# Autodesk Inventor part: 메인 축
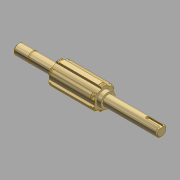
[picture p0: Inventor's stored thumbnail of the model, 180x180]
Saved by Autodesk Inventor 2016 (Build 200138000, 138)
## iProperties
Created: 2015-11
Part Number: 메인 축
Document SubType Name: 모델링
Designer: mdu
Mass: 21.4461 g
Surface Area: 72.5104 cm^2
Volume: 21.4461 cm^3
Density: 1 g/cm^3
Material: 일반
Appearance: 기본값
변환 표준: STEP AP214IS
파일 이름: C:\Users\SeoGD\Desktop\?쒗뿕\硫붿씤 異?.stp
전처리기: Build: 253, Release: 2010 SP1 - Date: Wed 07/29/2009
전송 단위: 밀리미터
불확실성: 0.01
Author: mdu
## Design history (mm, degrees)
sketch "스케치1"
  geometry: L1 (-69.5, 0)-(69.5, 0); L2 (69.5, 0)-(69.5, 5); L3 (69.5, 5)-(55.5, 5); L4 (55.5, 5)-(55.5, 4.8); L5 (55.5, 4.8)-(54.35, 4.8); L6 (54.35, 4.8)-(54.35, 5); L7 (54.35, 5)-(30.5, 5); L8 (30.5, 5)-(30.5, 9); L9 (30.5, 9)-(-13.5, 9); L10 (-13.5, 9)-(-13.5, 7); L11 (-13.5, 7)-(-17.5, 7); L12 (-17.5, 7)-(-17.5, 5); L13 (-17.5, 5)-(-69.5, 5); L14 (-69.5, 5)-(-69.5, 0); 2 further points
  constraints: 28 end point, 9 parallel, 4 collinear, 2 perpendicular, 1 coincident, 1 horizontal, 1 midpoint
  dimensions: "d2" = 1.15 distance between parallel lines of L6 L4; "d3" = 10 diameter of L3 L1; "d4" = 9.6 diameter of L5 L1; "d6" = 44 distance between parallel lines of L10 L8; "d7" = 4 distance between parallel lines of L12 L10; "d8" = 14 diameter of L11 L1; "d9" = 18 diameter of L9 L1; "d33" = 52 distance from line of L12.end L14; "d37" = 39 distance between parallel lines of L8 L2; "d38" = 14 distance between parallel lines of L2 L4
revolve "회전1" sketch "스케치1" stored, may be unused: angle "d10" = 90 deg
sketch "스케치2"
  geometry: L1 (2.5, 10.712)-(2.5, 8.646); L2 (-2.5, 10.712)-(-2.5, 8.646); A1 r 9 centre (0, 0) between (2.5, 8.646) and (-2.5, 8.646) reference; A2 r 11 centre (0, 0) between (2.5, 10.712) and (-2.5, 10.712); 1 further point
  constraints: 4 end point, 4 point on circle, 2 parallel, 1 centre point, 1 coincident, 1 vertical
  dimensions: "d11" = 22 diameter of A2; "d12" = 5 distance between parallel lines of L1 L2
extrude "돌출1" join sketch "스케치2" stored distance "d13" = 10; taper "d14" = 0 deg
chamfer "모따기1" distance "d15" = 1; stored, may be unused: second distance "d16" = 2, angle "d17" = 45 deg
node "작업 평면1"
node "작업 평면2"
sketch "스케치3"
  geometry: L1 (2.5, 10.712)-(2.5, 10.198); L2 (-2.5, 10.712)-(-2.5, 10.198); A1 r 11 centre (0, 0) between (2.5, 10.712) and (-2.5, 10.712) reference; A2 r 10.5 centre (0, 0) between (2.5, 10.198) and (-2.5, 10.198); 1 further point
  constraints: 4 end point, 2 point on circle, 1 centre point, 1 coincident, 1 parallel, 1 vertical
  dimensions: "d19" = 21 diameter of A2
extrude "돌출2" cut sketch "스케치3" distance "d20" = 1.35; taper "d21" = 0 deg
node "작업 평면3"
sketch "스케치4"
  geometry: L1 (-26, -5)-(-26, 5) reference; L2 (-26, 1.5)-(-12.5, 1.5); L3 (-12.5, -1.5)-(-26, -1.5); A1 r 1.5 centre (-12.5, 0) between (-12.5, -1.5) and (-12.5, 1.5); 2 further points
  constraints: 4 end point, 2 perpendicular, 2 point on circle, 2 point on line, 2 tangent, 1 centre point, 1 horizontal alignment, 1 midpoint
  dimensions: "d25" = 3 distance between parallel lines of L3 L2; "d26" = 15 dimension on A1 L1
extrude "돌출3" cut sketch "스케치4" distance "d27" = 1.8; taper "d28" = 0 deg
chamfer "모따기2" distance "d29" = 1; stored, may be unused: second distance "d30" = 2, angle "d31" = 45 deg
node "솔리드1"
node "솔리드 본체"
node "곡면 본체"
mirror "대칭1"
pattern_circular "원형 패턴1" dims "d23" = 360 deg
node "솔리드2"
other parameters: "d18" = -1.65
